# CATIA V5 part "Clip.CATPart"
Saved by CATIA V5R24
Part number: Clip
Bounding box of the stored display mesh (mm): x -7.9 to 7.9, y -19 to -14.029, z 0 to 4.52
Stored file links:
  C:\Users\Jules\Documents\ECL\Watch\Clip.CATPart
  C:\Users\Jules\Documents\ECL\Watch\Midle link.CATPart
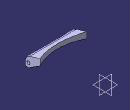
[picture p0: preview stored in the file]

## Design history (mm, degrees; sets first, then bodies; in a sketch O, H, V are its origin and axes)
Body1 (main body)
  Sketch1 on xy-plane, origin (0, 0, 0), H (1, 0, 0), V (0, 1, 0)
    construction arc A1 centre (0, 0) radius 16 from (-13.9491, 7.8372) to (-13.9491, -7.8372) ccw
    point P1 (-8, 13.8564)
    construction line L1 (-8, 13.8564) -> (-8, 19)
    point P2 (-8, 19)
    construction line L2 (-8, 19) -> (-9.5, 19)
    point P3 (-9.5, 19)
    construction line L3 (-9.5, 19) -> (-10.7872, 15.0465)
    point P4 (-12.3901, 10.1236)
    construction arc A2 centre (-48.822, 27.4301) radius 40 from (-13.9491, 7.8372) to (-10.7872, 15.0465) ccw
    point P5 (-13.9491, 7.8372)
    point P6 (-10.7872, 15.0465)
    point P7 (-8, 13.8564)
    point P9 (10.7872, 15.0465)
    point P10 (13.9491, 7.8372)
    construction arc A3 centre (48.822, 27.4301) radius 40 from (13.9491, 7.8372) to (10.7872, 15.0465) cw
    point P12 (9.5, 19)
    construction line L4 (9.5, 19) -> (10.7872, 15.0465)
    point P13 (8, 19)
    construction line L5 (8, 19) -> (9.5, 19)
    point P14 (8, 13.8564)
    construction line L6 (8, 13.8564) -> (8, 19)
    point P15 (10.7872, -15.0465)
    point P16 (13.9491, -7.8372)
    construction arc A4 centre (48.822, -27.4301) radius 40 from (13.9491, -7.8372) to (10.7872, -15.0465) ccw
    point P18 (9.5, -19)
    point P19 (8, -19)
    construction line L7 (8, -19) -> (9.5, -19)
    construction line L8 (9.5, -19) -> (10.7872, -15.0465)
    point P20 (8, -13.8564)
    construction line L9 (8, -13.8564) -> (8, -19)
    point P21 (-8, -19)
    point P22 (-8, -13.8564)
    construction line L10 (-8, -13.8564) -> (-8, -19)
    point P23 (-9.5, -19)
    construction line L11 (-8, -19) -> (-9.5, -19)
    point P24 (-10.7872, -15.0465)
    construction line L12 (-9.5, -19) -> (-10.7872, -15.0465)
    point P25 (-13.9491, -7.8372)
    construction arc A5 centre (-48.822, -27.4301) radius 40 from (-13.9491, -7.8372) to (-10.7872, -15.0465) cw
    construction arc A6 centre (0, 0) radius 16 from (8, 13.8564) to (-8, 13.8564) ccw
    construction arc A7 centre (0, 0) radius 16 from (13.9491, -7.8372) to (13.9491, 7.8372) ccw
    construction arc A8 centre (0, 0) radius 16 from (-8, -13.8564) to (8, -13.8564) ccw
    point P27 (-7.9, -19)
    line L13 (-7.9, -19) -> (-7.9, -14.0285)
    line L14 (-7.9, -19) -> (7.9, -19)
    line L15 (7.9, -19) -> (7.9, -14.0285)
    arc A9 centre (0, 0) radius 16.1 from (-7.9, -14.0285) to (7.9, -14.0285) ccw
    point P31 (0, 0)
    point P32 (0, -16.1)
    radius A2 = 40
    radius A1 = 16
    distance L1 V = 8
    distance H P3 = 19
    length L2 = 1.5
    distance A8 A9 = 0.1
    distance L15 L9 = 0.1
    distance L13 L10 = 0.1
    coincidence: P1 A1, P4 A1, L3 P4, P7 P1, A1 A6, A1 A7, A1 A8, P27 L7, A9 P32, P32 V, P31 O
    vertical: L1 V, L13 V, L15 V
    horizontal: L2 H, L14 H
    tangency: A2 L3, A2 A1
    symmetry: P6 P9 V, P5 P10 V, A2 A3 V, P3 P12 V, L3 L4 V, P2 P13 V, L2 L5 V, P1 P14 V, L1 L6 V, P9 P15 H, P10 P16 H, A3 A4 H, P12 P18 H, P13 P19 H, L5 L7 H, L4 L8 H, P14 P20 H, L6 L9 H, P2 P21 H, P1 P22 H, L1 L10 H, P3 P23 H, L2 L11 H, P6 P24 H, L3 L12 H, P5 P25 H, A2 A5 H
  Pad1: profile Sketch1, direction (0, 0, 1), length 5.5
  Sketch2 on zx-plane, origin (0, 0, 0), H (-1, 0, 0), V (0, 0, 1)
    point P1 (-16, 2.5)
    line L1 (-16, 2.5) -> (-19.5704, 0)
    point P2 (-19.5704, 0)
    line L2 (-19.5704, 0) -> (-13.5, 0)
    line L3 (-13.5, 0) -> (-16, 2.5)
    angle L1 L2 = 35
    angle L3 L2 = 45
    distance L2 P1 = 2.5
    coincidence: P2 H
    horizontal: L2 H
  Groove1: profile Sketch2, axis Sketch2.V, angle 360
  Sketch3 on yz-plane, origin (0, 0, 0), H (0, 1, 0), V (0, 0, 1)
    point P1 (-19, 3)
    line L1 (-19, 3) -> (0, 8.8089)
    point P2 (0, 8.8089)
    reference projected line E1 through (0, 0) direction (0, 1) from axis of face of Groove1 from Sketch2.L3
    point P5 (0, 8.8089)
    point P6 (19, 3)
    line L2 (19, 3) -> (0, 8.8089)
    distance P1 H = 3
    angle L1 H = 17
    coincidence: P2 V, P2 P5
    symmetry: P2 P5 E1, P1 P6 E1, L1 L2 E1
  Pocket1: profile Sketch3, direction (-1, 0, 0), length 10, mirrored extent, thin wall 0, second thickness 5
  Fillet1: radius 2, on edge [face of Pocket1 | face of Pad1 from Sketch1.L14]
  Sketch4 on yz-plane, origin (0, 0, 0), H (0, 1, 0), V (0, 0, 1)
    line L1 (-21, 2.85) -> (-18, 2.85)
    arc A1 centre (-18, 1.4) radius 1.45 from (-18, 2.85) to (-16.5731, 1.658) cw
    point P3 (-18, 1.4)
    point P4 (-18.0483, -0.0492)
    point P5 (-21.0467, 0.0508)
    arc A2 centre (-21, 1.45) radius 1.4 from (-21.7039, 0.2398) to (-21, 2.85) cw
    construction circle A3 centre (-18, 1.4) radius 0.55
    construction circle A4 centre (-21, 1.45) radius 0.55
    line L2 (-16.5731, 1.658) -> (-16.021, -1.3948)
    line L3 (-16.021, -1.3948) -> (-21.7039, 0.2398)
    radius A1 = 1.45
    distance P3 V = 18
    radius A3 = 0.55
    radius A4 = 0.55
    distance P3 H = 1.4
    distance P4 P5 = 3
    horizontal: L1 H
    tangency: A1 L1, A2 L1, L2 A1
    coincidence: L3 P5
  Pocket2: profile Sketch4, direction (-1, 0, 0), length 4.5, mirrored extent
  Sketch5 on yz-plane, origin (0, 0, 0), H (0, 1, 0), V (0, 0, 1)
    construction line L1 (-21, 2.85) -> (-18, 2.85)
    construction arc A1 centre (-18, 1.4) radius 1.45 from (-18, 2.85) to (-16.5731, 1.658) cw
    point P3 (-18, 1.4)
    point P4 (-18.0483, -0.0492)
    point P5 (-21.0467, 0.0508)
    construction arc A2 centre (-21, 1.45) radius 1.4 from (-21.7039, 0.2398) to (-21, 2.85) cw
    circle A3 centre (-18, 1.4) radius 0.55
    construction circle A4 centre (-21, 1.45) radius 0.55
    construction line L2 (-16.5731, 1.658) -> (-16.021, -1.3948)
    construction line L3 (-16.021, -1.3948) -> (-21.7039, 0.2398)
    radius A1 = 1.45
    distance P3 V = 18
    radius A3 = 0.55
    radius A4 = 0.55
    distance P3 H = 1.4
    distance P4 P5 = 3
    horizontal: L1 H
    tangency: A1 L1, A2 L1, L2 A1
    coincidence: L3 P5
  Pocket3: profile Sketch5, direction (-1, 0, 0), length 8.7, mirrored extent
